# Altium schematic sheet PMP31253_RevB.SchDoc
size 431 x 279 mm; Date: Not shown in title block; ApprovedBy: Not shown in title block; CheckedBy: Not shown in title block; Author: Not shown in title block; CompanyName: Not shown in title block; Engineer: Not shown in title block; Organization: Not shown in title block; Address1: Not shown in title block; Address2: Not shown in title block; Address3: Not shown in title block; Address4: Not shown in title block; DocumentNumber: 2; Revision: Use project parameter SCH_Rev; SheetNumber: 1; SheetTotal: 1; PageSetup: Record=PageOptions¦CenterHorizontal=True¦CenterVertical=True¦PrintScale=1.00¦XCorrection=1.00¦YCorrection=1.00¦PrintKind=0¦BorderSize=5000000¦LeftOffset=0¦BottomOffset=0¦Orientation=2¦PaperLength=1000¦PaperWidth=1000¦Scale=100¦PaperSource=15¦PrintQuality=600¦MediaType=1¦DitherType=10¦PaperKind=Letter¦PrintScaleMode=1
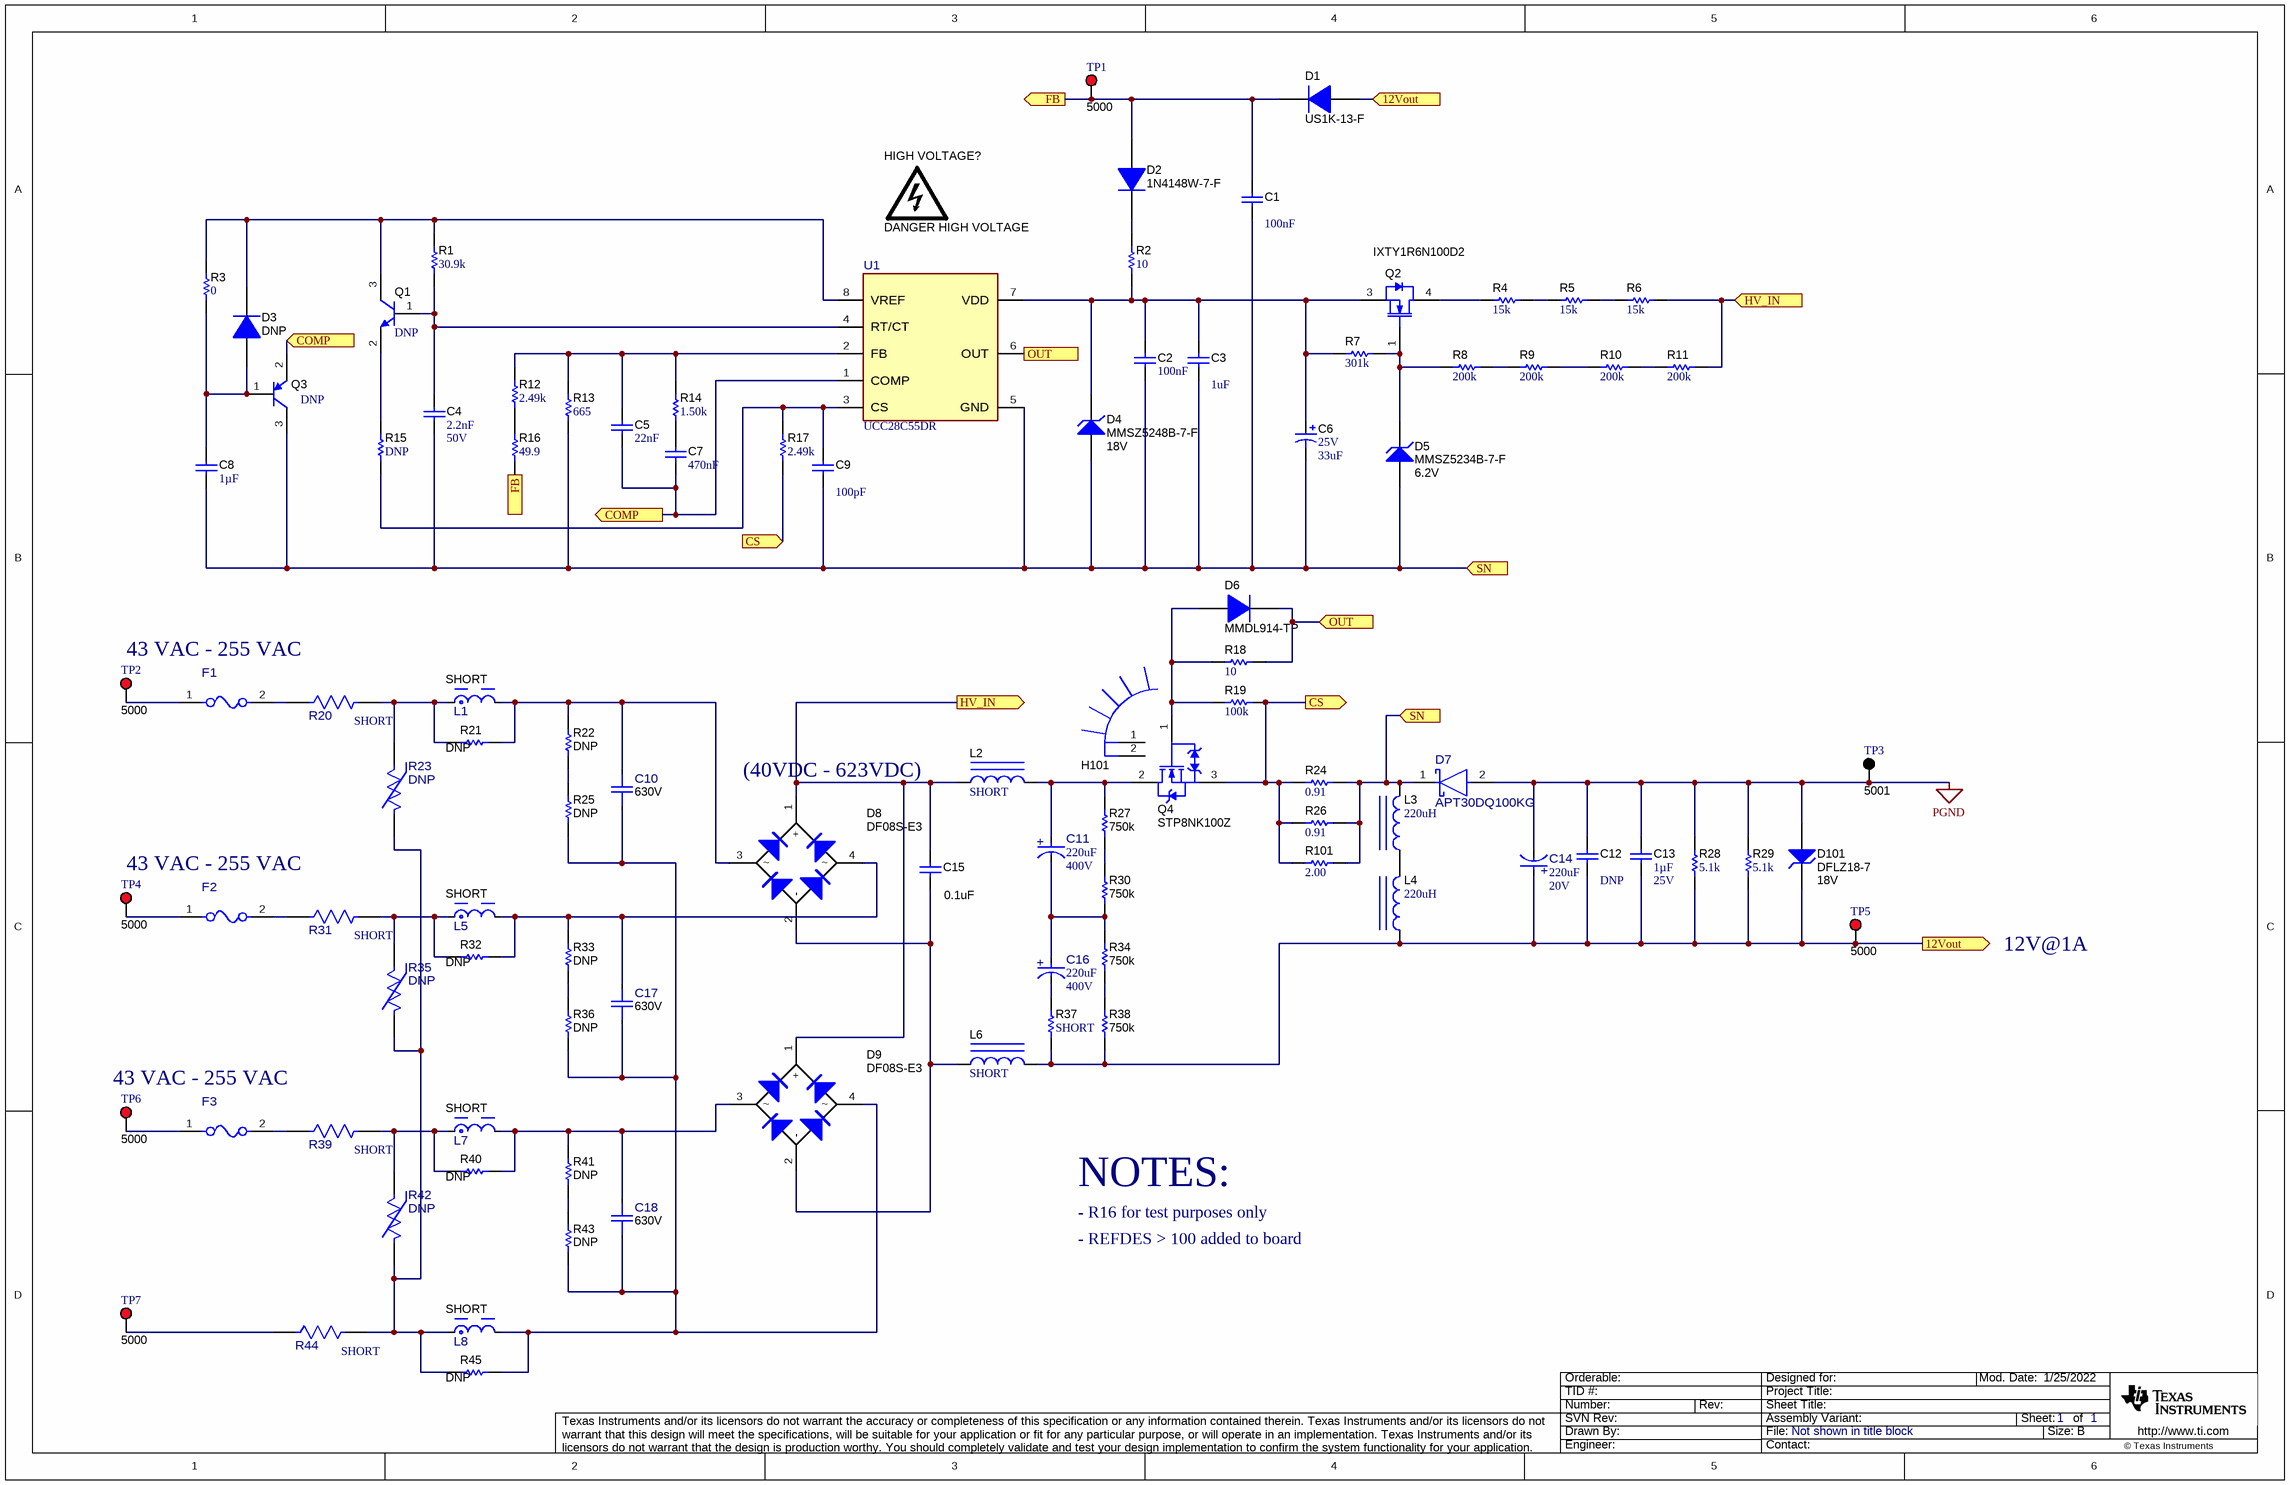
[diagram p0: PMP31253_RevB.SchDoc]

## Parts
C1  Cap_F: 100nF  [0805_HV]  (hidden comment: 08055C104KAT2A)
C2  Cap_F: 100nF  [0805_HV]  (hidden comment: C0805C104J5RACTU)
C3  ValueDisplayed: 1uF  [1206]  (hidden comment: GRM31MR71H105KA88L)
C4  Cap_F: 2.2nF  VDC_V: 50V  [0603]  (hidden comment: GRM188R71H222KA01D)
C5  Cap_F: 22nF  [0603]  (hidden comment: C0603X223K5RACTU)
C6  VDC_V: 25V  ValueDisplayed: 33uF  [CAPSMT_62_F55]  (hidden comment: EMVY250ADA330MF55G)
C7  Cap_F: 470nF  [0603]  (hidden comment: C1608X7R1H474K080AC)
C8  Cap_F: 1µF  [0805_HV]  (hidden comment: GRM21BR71H105KA12L)
C9  ValueDisplayed: 100pF  [0603]  (hidden comment: GRM1885C1H101JA01D)
C10  VDC_V: 630V  [FP-890334025027RP_RADIAL-MFG]  (hidden comment: 890334025027RP)
C11  ValueDisplayed: 220uF  VDC_V: 400V  [FP-EKMQ401VSN221MP45S_RADIAL-MFG]  (hidden comment: EKMQ401VSN221MP45S)
C12  GCM31MR71E105KA37L  [1206]  (value not drawn)
C13  Cap_F: 1µF  VDC_V: 25V  [0805_HV]  (hidden comment: GRM21BR71E105KA99L)
C14  ValueDisplayed: 220uF  VDC_V: 20V  [FP-A768KE227M1DLAE029_SMT_CAP_8MM3_8MM3-MFG]  (hidden comment: A768KE227M1DLAE029)
C15  value 0.1uF  [B32913_2650x700x1600]  (hidden comment: B32913C5104K000)
C16  ValueDisplayed: 220uF  VDC_V: 400V  [FP-EKMQ401VSN221MP45S_RADIAL-MFG]  (hidden comment: EKMQ401VSN221MP45S)
C17  VDC_V: 630V  [FP-890334025027RP_RADIAL-MFG]  (hidden comment: 890334025027RP)
C18  VDC_V: 630V  [FP-890334025027RP_RADIAL-MFG]  (hidden comment: 890334025027RP)
D1  US1K-13-F  [SMA]
D2  1N4148W-7-F  [SOD-123]
D3  DNP  [SOD-323]
D4  MMSZ5248B-7-F  value 18V  [SOD-123]
D5  MMSZ5234B-7-F  value 6.2V  [SOD-123]
D6  MMDL914-TP  [SOD-323]
D7  APT30DQ100KG  [FP-C6D04065A_TO-220-2-MFG]
D8  DF08S-E3  [DF-S]
D9  DF08S-E3  [DF-S]
D101  DFLZ18-7  value 18V  [PowerDI123]
F1  04611.25ER  [FP-04611.25ER_SMT_FUSE_10MM10_3MM12-MFG]  (value not drawn)
F2  04611.25ER  [FP-04611.25ER_SMT_FUSE_10MM10_3MM12-MFG]  (value not drawn)
F3  04611.25ER  [FP-04611.25ER_SMT_FUSE_10MM10_3MM12-MFG]  (value not drawn)
H101  V6560X  [ASMN_V6560X]  (value not drawn)
HIGH_VOLTAGE?  DANGER HIGH VOLTAGE  [IEC_HighVoltage_Small]  (no BOM)
L1  value SHORT  [FP-7447471222_RADIAL-MFG]  (hidden comment: 7447471222)
L2  ValueDisplayed: SHORT  [WE-TI_1014]  (hidden comment: 7447480101)
L3  ValueDisplayed: 220uH  [WE_PD-HV_1210]  (hidden comment: 7687709221)
L4  ValueDisplayed: 220uH  [WE_PD-HV_1210]  (hidden comment: 7687709221)
L5  value SHORT  [FP-7447471222_RADIAL-MFG]  (hidden comment: 7447471222)
L6  ValueDisplayed: SHORT  [WE-TI_1014]  (hidden comment: 7447480101)
L7  value SHORT  [FP-7447471222_RADIAL-MFG]  (hidden comment: 7447471222)
L8  value SHORT  [FP-7447471222_RADIAL-MFG]  (hidden comment: 7447471222)
Q1  value DNP  [SOT-23]  (hidden comment: MMBT3904-7-F)
Q2  IXTY1R6N100D2  [DPAK]
Q3  value DNP  [SOT-23]  (hidden comment: MMBT2907A)
Q4  STP8NK100Z  [TO-220AB]
R1  ValueDisplayed: 30.9k  [0603]  (hidden comment: CRCW060330K9FKEA)
R2  ValueDisplayed: 10  [0805_HV]  (hidden comment: RC0805JR-0710RL)
R3  ValueDisplayed: 0  [0603]  (hidden comment: CRCW06030000Z0EA)
R4  ValueDisplayed: 15k  [PR03]  (hidden comment: PR03000201502JAC00)
R5  ValueDisplayed: 15k  [PR03]  (hidden comment: PR03000201502JAC00)
R6  ValueDisplayed: 15k  [PR03]  (hidden comment: PR03000201502JAC00)
R7  ValueDisplayed: 301k  [1206]  (hidden comment: CRCW1206301KFKEA)
R8  ValueDisplayed: 200k  [1206]  (hidden comment: CRCW1206200KJNEA)
R9  ValueDisplayed: 200k  [1206]  (hidden comment: CRCW1206200KJNEA)
R10  ValueDisplayed: 200k  [1206]  (hidden comment: CRCW1206200KJNEA)
R11  ValueDisplayed: 200k  [1206]  (hidden comment: CRCW1206200KJNEA)
R12  ValueDisplayed: 2.49k  [0603]  (hidden comment: CRCW06032K49FKEA)
R13  ValueDisplayed: 665  [0603]  (hidden comment: CRCW0603665RFKEA)
R14  ValueDisplayed: 1.50k  [0603]  (hidden comment: CRCW06031K50FKEA)
R15  CRCW06031M50JNEA  [0603]  (value not drawn)
R16  ValueDisplayed: 49.9  [0603]  (hidden comment: CRCW060349R9FKEA)
R17  ValueDisplayed: 2.49k  [0603]  (hidden comment: CRCW06032K49FKEA)
R18  ValueDisplayed: 10  [0805_HV]  (hidden comment: CRCW080510R0JNEA)
R19  ValueDisplayed: 100k  [0603]  (hidden comment: CRCW0603100KFKEA)
R20  Res_ohm: SHORT  [FP-SQMW547RJ_RADIAL-MFG]  (hidden comment: SQMW5xxx)
R21  value DNP  [1206]  (hidden comment: CRCW120610K0FKEAHP)
R22  ValueDisplayed: DNP  [1206]  (hidden comment: CRCW1206100KJNEA)
R23  DNP  [FP-B72210S0461K101_RADIAL-MFG]
R24  ValueDisplayed: 0.91  [1210]  (hidden comment: ERJ-14BQ)
R25  ValueDisplayed: DNP  [1206]  (hidden comment: CRCW1206100KJNEA)
R26  ValueDisplayed: 0.91  [1210]  (hidden comment: ERJ-14BQ)
R27  ValueDisplayed: 750k  [1206]  (hidden comment: CRCW1206)
R28  ValueDisplayed: 5.1k  [1206]  (hidden comment: CRCW12065K10JNEA)
R29  ValueDisplayed: 5.1k  [1206]  (hidden comment: CRCW12065K10JNEA)
R30  ValueDisplayed: 750k  [1206]  (hidden comment: CRCW1206)
R31  Res_ohm: SHORT  [FP-SQMW547RJ_RADIAL-MFG]  (hidden comment: SQMW5xxx)
R32  value DNP  [1206]  (hidden comment: CRCW120610K0FKEAHP)
R33  ValueDisplayed: DNP  [1206]  (hidden comment: CRCW1206100KJNEA)
R34  ValueDisplayed: 750k  [1206]  (hidden comment: CRCW1206)
R35  DNP  [FP-B72210S0461K101_RADIAL-MFG]
R36  ValueDisplayed: DNP  [1206]  (hidden comment: CRCW1206100KJNEA)
R37  ValueDisplayed: SHORT  [2512]  (hidden comment: CRM2512-FX-15R0)
R38  ValueDisplayed: 750k  [1206]  (hidden comment: CRCW1206)
R39  Res_ohm: SHORT  [FP-SQMW547RJ_RADIAL-MFG]  (hidden comment: SQMW5xxx)
R40  value DNP  [1206]  (hidden comment: CRCW120610K0FKEAHP)
R41  ValueDisplayed: DNP  [1206]  (hidden comment: CRCW1206100KJNEA)
R42  DNP  [FP-B72210S0461K101_RADIAL-MFG]
R43  ValueDisplayed: DNP  [1206]  (hidden comment: CRCW1206100KJNEA)
R44  Res_ohm: SHORT  [FP-SQMW547RJ_RADIAL-MFG]  (hidden comment: SQMW5xxx)
R45  value DNP  [1206]  (hidden comment: CRCW120610K0FKEAHP)
R101  ValueDisplayed: 2.00  [1210]  (hidden comment: ERJ-14BQF2R0U)
TP1  5000  [Keystone5000]
TP2  5000  [Keystone5000]
TP3  5001  [Keystone5001]
TP4  5000  [Keystone5000]
TP5  5000  [Keystone5000]
TP6  5000  [Keystone5000]
TP7  5000  [Keystone5000]
U1  UCC28C55DR  [D0008A-MFG]

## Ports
12Vout (in), 12Vout (out), COMP (in), COMP (out), CS (in), CS (out), FB (in), FB (out), HV_IN (in), HV_IN (out), OUT (in), OUT (out), SN (in)

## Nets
PGND: C12.1 C13.1 C14.1(CATHODE) D7.2(ANODE) D101.2(A) R28.2 R29.2 TP3.1
12Vout: C12.2 C13.2 C14.2(ANODE) D1.2(A) D101.1(K) L4.1 L6.2 R28.1 R29.1 R37.1 R38.1 TP5.1 ; port 12Vout
COMP: C5.2 C7.2 Q3.2(E) U1.1(COMP) ; port COMP
CS: Q4.3(S) R17.1 R19.2 R24.1 R26.1 R101.1 ; port CS
FB: C1.1 D1.1(K) D2.2(A) R16.1 TP1.1 ; port FB
HV_IN: C15.1 D8.1(+) D9.1(+) L2.1 R6.2 R11.2 ; port HV_IN
OUT: D6.1(K) R18.2 U1.6(OUT) ; port OUT
SN: C1.2 C2.2 C3.2 C4.2 C6.2(-) C8.2 C9.2 D4.2(A) D5.2(A) D7.1(CATHODE) L3.2 Q3.3(C) R13.1 R24.2 R26.2 R101.2 U1.5(GND) ; port SN
NetC2_1: C2.1 C3.1 C6.1(+) D4.1(K) Q2.3(S) R2.1 R7.1 U1.7(VDD)
NetC4_1: C4.1 Q1.1(B) R1.1 U1.4(RT/CT)
NetC5_1: C5.1 R12.2 R13.2 R14.2 U1.2(FB)
NetC7_1: C7.1 R14.1
NetC8_1: C8.1 D3.2(A) Q3.1(B) R3.1
NetC9_1: C9.1 R15.1 R17.2 U1.3(CS)
NetC10_1: C10.1 C17.1 C18.1 D9.4 L8.2 R25.1 R36.1 R43.1 R45.2
NetC10_2: C10.2 D8.3 L1.2 R21.2 R22.2
NetC11_1: C11.1(CATHODE) C16.2(ANODE) R30.1 R34.2
NetC11_2: C11.2(ANODE) L2.2 Q4.2(D) R27.2
NetC15_2: C15.2 D8.2(-) D9.2(-) L6.1
NetC16_1: C16.1(CATHODE) R37.2
NetC17_2: C17.2 D8.4 L5.2 R32.2 R33.2
NetC18_2: C18.2 D9.3 L7.2 R40.2 R41.2
NetD2_1: D2.1(K) R2.2
NetD3_1: D3.1(K) Q1.3(C) R1.2 R3.2 U1.8(VREF)
NetD5_1: D5.1(K) Q2.1(G) R7.2 R8.1
NetD6_2: D6.2(A) Q4.1(G) R18.1 R19.1
NetF1_1: F1.1 TP2.1
NetF1_2: F1.2 R20.1
NetF2_1: F2.1 TP4.1
NetF2_2: F2.2 R31.1
NetF3_1: F3.1 TP6.1
NetF3_2: F3.2 R39.1
NetL1_1: L1.1 R20.2 R21.1 R23.2
NetL3_1: L3.1 L4.2
NetL5_1: L5.1 R31.2 R32.1 R35.2
NetL7_1: L7.1 R39.2 R40.1 R42.2
NetL8_1: L8.1 R23.1 R35.1 R42.1 R44.2 R45.1
NetQ1_2: Q1.2(E) R15.2
NetQ2_4: Q2.4(D) R4.1
NetR4_2: R4.2 R5.1
NetR5_2: R5.2 R6.1
NetR8_2: R8.2 R9.1
NetR9_2: R9.2 R10.1
NetR10_2: R10.2 R11.1
NetR12_1: R12.1 R16.2
NetR22_1: R22.1 R25.2
NetR27_1: R27.1 R30.2
NetR33_1: R33.1 R36.2
NetR34_1: R34.1 R38.2
NetR41_1: R41.1 R43.2
NetR44_1: R44.1 TP7.1

Not connected (* = marked no-connect by the designer): H101 1 2

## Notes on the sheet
- 43 VAC - 255 VAC
- (40VDC - 623VDC)
- 12V@1A
- NOTES:
- - R16 for test purposes only
- - REFDES > 100 added to board

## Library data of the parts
C1 = CMP-0007632-2: CAP, CERM, 0.1 uF, 50 V, +/- 10%, X7R, 0805; Manufacturer: AVX; TaMin_C: -55°C; ESR_ohm: 24m; Polarized: N; SizeAreaWB_mm2: 6.75; Value1: 0.024 ohm; U/M: EA; Value: 0.1uF; TaMax_C: 125°C; SizeZ_mm: 1.45; SizeX_mm: 2; SizeY_mm: 1.25; Cap_Case: 0805; Value2: 50V; SizeArea_mm2: 2.5; AEC Category: Q200
C2 = CMP-0007721-2: CAP, CERM, 0.1 uF, 50 V, +/- 5%, X7R, 0805; Manufacturer: Kemet; TaMin_C: -55°C; ESR_ohm: 64m; Polarized: N; SizeAreaWB_mm2: 6.75; Value1: 0.064 ohm; U/M: EA; Value: 0.1uF; TaMax_C: 125°C; SizeZ_mm: 1.45; SizeX_mm: 2; SizeY_mm: 1.25; Cap_Case: 0805; Value2: 50V; SizeArea_mm2: 2.5; IRMS_A: 1.64A; AEC Category: Q200
C3 = CMP-0008992-2: CAP, CERM, 1 uF, 50 V, +/- 10%, X7R, 1206; Manufacturer: MuRata; TaMin_C: -55°C; Polarized: N; SizeAreaWB_mm2: 10.92; Value1: Unknown; U/M: EA; Value: 1uF; TaMax_C: 125°C; SizeZ_mm: 1.35; SizeX_mm: 3.2; SizeY_mm: 1.6; Value2: 50V; SizeArea_mm2: 5.12; Cap_F: 1µF; AEC Category: Q200
C4 = CMP-0007443-4: CAP, CERM, 2200 pF, 50 V, +/- 10%, X7R, 0603; Manufacturer: MuRata; TaMin_C: -55°C; Polarized: N; SizeAreaWB_mm2: 4.68; Value1: Unknown; U/M: EA; Value: 2200pF; TaMax_C: 125°C; SizeZ_mm: 1; SizeX_mm: 1.6; SizeY_mm: 0.8; SizeArea_mm2: 1.28; AEC Category: Q200
C5 = CMP-0006984-4: CAP, CERM, 0.022 uF, 50 V, +/- 10%, X7R, 0603; Manufacturer: Kemet; TaMin_C: -55°C; Polarized: N; SizeAreaWB_mm2: 4.68; Value1: Unknown; U/M: EA; TaMax_C: 125°C; SizeZ_mm: 1; SizeX_mm: 1.6; SizeY_mm: 0.8; Value2: 50V; SizeArea_mm2: 1.28; AEC Category: Q200
C6 = CMP-0010994-1: CAP, AL, 33 uF, 25 V, +/- 20%, 1 ohm, SMD; Manufacturer: Chemi-Con; TaMin_C: -55°C; ESR_ohm: 1; Polarized: Y; SizeAreaWB_mm2: 77.44; Value1: 1 ohm; U/M: EA; Value: 33uF; TaMax_C: 105°C; SizeZ_mm: 5.5; SizeX_mm: 6.8; Cap_Case: F55; SizeArea_mm2: 46.24; CompType: Capacitor; Cap_F: 33µF; IRMS_A: 140mA; AEC Category: Q200
C7 = CMP-0007050-4: CAP, CERM, 0.47 uF, 50 V, +/- 10%, X7R, 0603; Manufacturer: TDK; TaMin_C: -55°C; ESR_ohm: 10.974m; Polarized: N; SizeAreaWB_mm2: 4.68; Value1: 0.010974 ohm; U/M: EA; Value: 0.47uF; TaMax_C: 125°C; SizeZ_mm: 1; SizeX_mm: 1.6; SizeY_mm: 0.8; Value2: 50V; SizeArea_mm2: 1.28; IRMS_A: 1.5748A; AEC Category: Q200
C8 = CMP-0008350-2: CAP, CERM, 1 uF, 50 V, +/- 10%, X7R, 0805; Manufacturer: MuRata; TaMin_C: -55°C; Polarized: N; SizeAreaWB_mm2: 6.75; Value1: Unknown; U/M: EA; Value: 1uF; TaMax_C: 125°C; SizeZ_mm: 1.45; SizeX_mm: 2; SizeY_mm: 1.25; Cap_Case: 0805; Value2: 50V; SizeArea_mm2: 2.5; AEC Category: Q200
C9 = CMP-0007171-4: CAP, CERM, 100 pF, 50 V, +/- 5%, C0G/NP0, 0603; Manufacturer: MuRata; TaMin_C: -55°C; Polarized: N; SizeAreaWB_mm2: 4.68; Value1: Unknown; U/M: EA; Value: 100pF; TaMax_C: 125°C; SizeZ_mm: 1; SizeX_mm: 1.6; SizeY_mm: 0.8; Value2: 50V; SizeArea_mm2: 1.28; AEC Category: Q200
C10 C17 C18 = CMP-0096484-1: 0.22 µF Film Capacitor 630V Polypropylene (PP), Metallized Radial; Manufacturer: Wurth Electronics; AEC Qualified: No; Cap_F: 220nF; Voltage Ac Rating X: 310V; SizeZ_mm: 12mm; Tolerance_%: 10%; Value: 220nF; VAC_X: X2
C11 C16 = CMP-0001412-1: Cap Aluminum Lytic 220uF 400V 20% (22 X 45mm) Snap-In 10mm 1100mA 2000h 105°C; Manufacturer: United Chemi-Con; AEC Qualified: No; Cap_F: 220µF; IRMS_A: 1.1A; SizeZ_mm: 47mm; Dissipation Factor: 15%; Leakage Current: 889uA; Life: 2000Hours; Value: 220µF
C12 = CMP-0008817-1: DNP; Manufacturer: MuRata; TaMin_C: -55°C; Polarized: N; TempCo: X7R; SizeAreaWB_mm2: 10.92; Value1: Unknown; U/M: EA; TaMax_C: 125°C; Tolerance_%: 10%; SizeZ_mm: 1.35; SizeX_mm: 3.2; SizeY_mm: 1.6; Value2: 25V; SizeArea_mm2: 5.12; AEC Qualified: Y; Cap_F: 1µF; AEC Grade: 1; AEC Category: Q200
C13 = CMP-0008336-1: CAP, CERM, 1 uF, 25 V, +/- 10%, X7R, 0805; Manufacturer: MuRata; TaMin_C: -55°C; Polarized: N; SizeAreaWB_mm2: 6.75; Value1: Unknown; U/M: EA; Value: 1uF; TaMax_C: 125°C; SizeZ_mm: 1.45; SizeX_mm: 2; SizeY_mm: 1.25; Cap_Case: 0805; SizeArea_mm2: 2.5; AEC Category: Q200
C14 = CMP-0001409-1: 220 µF 20 V Aluminum - Polymer Capacitors Radial, Can - SMD 29mOhm 2000 Hrs @ 125°C; Manufacturer: KEMET; AEC Qualified: No; Cap_F: 220µF; IRMS_A: 1.6A; SizeZ_mm: 7mm; Tolerance_%: 20%; Esr: 29m; Leakage Current: 880uA; Life: 2000Hours; Value: 220µF
C15 = CMP-0012372-1: CAP, Film, 0.1 uF, 1000 V, +/- 10%, TH; Manufacturer: TDK; TaMin_C: -40°C; Polarized: N; SizeAreaWB_mm2: 256.5; Value1: Unknown; U/M: EA; TaMax_C: 110°C; SizeZ_mm: 16; SizeX_mm: 26.5; SizeY_mm: 7; Cap_Case: 26.5x7x16mm; Value2: 1000V; SizeArea_mm2: 185.5; Cap_F: 100nF; VDC_V: 1kV; AEC Category: Q200
D1 = CMP-0076980-2: Diode, Fast Rectifier, 800 V, 1 A, SMA; Manufacturer: Diodes Inc.; AEC Category: Q101; Io_A: 1A; Green_Lifecycle: Not Set; Value2: 1.7V; SizeAreaWB_mm2: 37.3428; Green_REACh: Incomplete; Vr_V: 800V; SizeY_mm: 2.92; Value: 800V; TJmax_C: 150°C; SizeZ_mm: 2.87; SizeX_mm: 5.59; SizeArea_mm2: 16.3228
D2 = CMP-0029001-1: Diode, Ultrafast, 100 V, 0.15 A, SOD-123; Manufacturer: Diodes Inc.; Io_A: 150mA; Green_Lifecycle: Active; SizeAreaWB_mm2: 13.095; Vr_V: 100V; Green_REACh: Passed; Value1: 0.15A; TJmax_C: 150°C; U/M: EA; Value: 100V; SizeZ_mm: 1.35; SizeX_mm: 3.85; SizeY_mm: 1.7; Vf_V: 1.25V; SizeArea_mm2: 6.545; AEC Category: Q101
D3 = CMP-0082069-2: Manufacturer: Micro Commercial Components; AEC Category: Q101; AEC Qualified: N; Value1: 0.15A; SizeX_mm: 2.7; Vr_V: 75V; Vf_V: 1V; SizeZ_mm: 1; SizeY_mm: 1.35; SizeAreaWB_mm2: 8.695; Type: Switching; TJmax_C: 150°C; RJC_CperW: 625; Io_A: 150mA; SizeArea_mm2: 3.645
D4 = CMP-0005755-4: Diode, Zener, 18 V, 500 mW, SOD-123; Manufacturer: Diodes Inc.; SizeAreaWB_mm2: 13.095; RJA_CperW: 350; SizeArea_mm2: 6.545; Power_W: 500mW; SizeX_mm: 3.85; SizeY_mm: 1.7; AEC Category: Q101; Value1: 0.5W; SizeZ_mm: 1.35
D5 = CMP-0005805-3: Diode, Zener, 6.2 V, 500 mW, SOD-123; Manufacturer: Diodes Inc.; SizeY_mm: 1.7; AEC Category: Q101; SizeAreaWB_mm2: 13.095; SizeZ_mm: 1.35; SizeArea_mm2: 6.545; RJA_CperW: 350; Power_W: 500mW; Value1: 0.5W; SizeX_mm: 3.85
D6 = CMP-0029045-1: Diode, Switching, 100 V, 0.2 A, SOD-323; Manufacturer: Micro Commercial Components; Io_A: 200mA; Green_Lifecycle: Not Set; SizeAreaWB_mm2: 8.695; Vr_V: 100V; Green_REACh: Incomplete; Value1: 0.2A; TJmax_C: 150°C; U/M: EA; Value: 100V; SizeZ_mm: 1; SizeX_mm: 2.7; SizeY_mm: 1.35; Vf_V: 1V; SizeArea_mm2: 3.645; AEC Category: Q101
D7 = CMP-0094567-1: Diode 1kV Through Hole TO-220-2; Part Number: APT30DQ100GK; Manufacturer: Wolfspeed; Standoff Height: 3.302mm; Forward Current: 30A; TJmax_C: 175°C; Vf_V: 1000V; SizeZ_mm: 19.431mm; AEC Qualified: No
D8 D9 = CMP-0029219-1: Diode, Switching-Bridge, 800 V, 1 A, DF-S; Manufacturer: Vishay-Semiconductor; Io_A: 1A; SizeAreaWB_mm2: 98.794; Vr_V: 600V; Green_REACh: Incomplete; TJmax_C: 150°C; U/M: EA; Value: 800V; Green_Lifecycle: Not Set; SizeZ_mm: 3.4; SizeX_mm: 7.4; SizeY_mm: 8.51; Vf_V: 1.1V; SizeArea_mm2: 62.974; AEC Category: Q101; RJC_CperW: 15
D101 = CMP-0005413-4: Diode, Zener, 18 V, 1 W, PowerDI123; Manufacturer: Diodes Inc.; RJA_CperW: 110; Power_W: 1W; SizeAreaWB_mm2: 13.066; AEC Category: Q101; SizeZ_mm: 0.98; SizeX_mm: 3.7; SizeY_mm: 1.78; SizeArea_mm2: 6.586
F1-F3 = CMP-0001488-1: Fuse Chip Slow Blow Acting 1.25A 600V SMD Solder Pad 10.1 X 3.12 X 3.12mm Ceramic T/R; Manufacturer: Littelfuse Inc; Interrupt_AC: 60A; Interrupt_DC: 100A; MeltingTyp: 16.5A2Sec; AEC Qualified: No; Res_ohm: 0.104Ω
H101 = CMP-0004065-1: HEATSINK, ALUM, TO-220; PartNumber: Heatsink TO220
HIGH_VOLTAGE? = CMP-0074835-1: IEC 61010-1 High Voltage Warning; SymbolCreator: a0412235
L1 L5 L7 L8 = CMP-0096506-1: 2.2 mH Shielded Drum Core, Wirewound Inductor 400 mA 2.7Ohm Max Radial, Vertical Cylinder; Manufacturer: Wurth Electronics; Self Resonant Frequency: 740kHz; Ind_H: 2.2mH; DCR_ohm: 5.7; AEC Qualified: Yes; Irms: 0.31A; Tolerance_%: 10%; TaMax_C: +85°C; TaMin_C: -40°C; AEC Grade: Grade 1; SizeZ_mm: 11.5mm; Shrouded: true; Test Frequency: 10kHz; Isat: 0.46A; Material: Ferrite
L2 L6 = CMP-0064523-2: Inductor, Wirewound, Ferrite, 100 uH, 2.4 A, 0.1 ohm, TH; Manufacturer: Wurth Elektronik; Isat: 2.5A @ 10% inductance drop; Irms: 2.4A @ 40C rise; Green_Lifecycle: Active; SizeAreaWB_mm2: 156.25; DCR_ohm: 0.1; Green_REACh: Passed; Value1: 0.1 ohm; Value: 100uH; Imax_A: 2.4A; SizeZ_mm: 14.5; SizeX_mm: 10.5; SizeArea_mm2: 110.25; Ind_H: 100µH; AEC Category: Q200
L3 L4 = CMP-0064845-2: Inductor, Wirewound, 220 uH, 1.3 A, 0.3 ohm, SMD; Manufacturer: Wurth Elektronik; Isat: 2A @ 10% inductance drop; Irms: 1.3A @ 40C rise; Green_Lifecycle: Active; SizeAreaWB_mm2: 196; DCR_ohm: 0.3; Green_REACh: Passed; Value1: 0.3 ohm; Value: 220uH; Imax_A: 1.3A; SizeZ_mm: 10.5; SizeX_mm: 12; SizeArea_mm2: 144; Ind_H: 220µH; AEC Qualified: N; AEC Category: Q200
Q1 = CMP-0000387-2: Transistor, NPN, 40 V, 0.2 A, SOT-23; Manufacturer: Diodes Inc.; TaMax_C: 150°C; Value2: 400; Value1: 0.2 A; Vcesat1_V: 200mV; SizeX_mm: 2.5; SizeY_mm: 3; TaMin_C: -55°C; IcRated_A: 200mA; CompType: BJT; SizeZ_mm: 1.1; SizeArea_mm2: 7.5; NPN: 1; Vceo_V: 40V; PNP: 0; SizeAreaWB_mm2: 14; U/M: EA
Q2 = CMP-0067585-1: MOSFET, N-CH, 1000V, DPAK; Alternate Manufacturer: None; Manufacturer: IXYS; QgTyp_nC: 27.0; SizeAreaWB_mm2: 101.7114; Value1: ? ohm; VdsMax_V: 1kV; U/M: EA; SizeArea_mm2: 64.8114; ChType: N
Q3 = CMP-0000331-2: Transistor, PNP, 60 V, 0.8 A, SOT-23; Manufacturer: Fairchild Semiconductor; TaMax_C: 150°C; Vcesat1_V: 1.6V; SizeX_mm: 2.5; SizeY_mm: 3; TaMin_C: -55°C; IcRated_A: 800mA; CompType: BJT; SizeZ_mm: 1.1; HfeMax: 300; SizeArea_mm2: 7.5; NPN: 0; Vceo_V: 60V; PNP: 1; AEC Category: Q101; SizeAreaWB_mm2: 14; U/M: EA
Q4 = CMP-0001292-3: MOSFET, N-CH, 1000 V, 6.5 A, TO-220AB; Alternate Manufacturer: None; Manufacturer: STMicroelectronics; SizeZ_mm: 19.4; ChType: N; Value2: 73 nC; VdsMax_V: 1kV; SizeX_mm: 10.2; SizeY_mm: 4.5; Vgs_V: 30V; Value: 1000V; SizeArea_mm2: 45.9; AEC Category: Q101; IdsMax_A: 6.5A; SizeAreaWB_mm2: 79.3; U/M: EA; QgTyp_nC: 73
R1 = CMP-0022325-4: RES, 30.9 k, 1%, 0.1 W, AEC-Q200 Grade 0, 0603; Manufacturer: Vishay-Dale; Power_W: 100mW; TempCo: 100 ppm/C; Value_Code: 30k9; Value: 30.9k; EIA_Code: E96; SizeX_mm: 1.6; SizeY_mm: 0.8; SizeZ_mm: 1; Value2: 0.1W; SizeArea_mm2: 1.28; AEC Qualified: Y; VDC_V: 75V; AEC Category: Q200; AEC Grade: 0
R2 = CMP-0020804-2: RES, 10, 5%, 0.125 W, 0805; Manufacturer: Yageo America; Power_W: 125mW; TempCo: 200 ppm/C; Value_Code: 10R0; U/M: EA; Value: 10; EIA_Code: E24; SizeX_mm: 2; SizeY_mm: 1.25; SizeZ_mm: 1.45; Value2: 0.125W; SizeArea_mm2: 2.5; VDC_V: 150V; AEC Category: Q200
R3 = CMP-0025697-4: RES, 0, 5%, 0.1 W, AEC-Q200 Grade 0, 0603; Manufacturer: Vishay-Dale; Power_W: 100mW; TempCo: 200 ppm/C; Value_Code: 0000; Value: 0; EIA_Code: E24; SizeX_mm: 1.6; SizeY_mm: 0.8; SizeZ_mm: 1; Value2: 0.1W; SizeArea_mm2: 1.28; AEC Qualified: Y; VDC_V: 75V; AEC Category: Q200
R4-R6 = CMP-0014427-2: RES, 15 k, 5%, 3 W, D5.20xL16.70mm; Manufacturer: Vishay-Bccomponents; Power_W: 3W; TempCo: 250 ppm/C; Value_Code: 15k0; U/M: EA; Value: 15k; EIA_Code: E24; AEC Qualified: N; VDC_V: 750V; AEC Category: Q200
R7 = CMP-0016895-2: RES, 301 k, 1%, 0.25 W, 1206; Manufacturer: Vishay-Dale; Power_W: 250mW; TempCo: 100 ppm/C; U/M: EA; Value: 301k; EIA_Code: E96; SizeX_mm: 3.2; SizeY_mm: 1.6; SizeZ_mm: 1.35; Value2: 0.25W; SizeArea_mm2: 5.12; VDC_V: 200V; AEC Category: Q200
R8-R11 = CMP-0018624-3: RES, 200 k, 5%, 0.25 W, AEC-Q200 Grade 0, 1206; Manufacturer: Vishay-Dale; Power_W: 250mW; TempCo: 200 ppm/C; Value: 200k; EIA_Code: E24; SizeX_mm: 3.2; SizeY_mm: 1.6; SizeZ_mm: 1.35; Value2: 0.25W; SizeArea_mm2: 5.12; AEC Qualified: Y; VDC_V: 200V; AEC Category: Q200; AEC Grade: 0
R12 R17 = CMP-0022277-4: RES, 2.49 k, 1%, 0.1 W, AEC-Q200 Grade 0, 0603; Manufacturer: Vishay-Dale; Power_W: 100mW; TempCo: 100 ppm/C; Value_Code: 2k49; Value: 2.49k; EIA_Code: E96; SizeX_mm: 1.6; SizeY_mm: 0.8; SizeZ_mm: 1; Value2: 0.1W; SizeArea_mm2: 1.28; AEC Qualified: Y; VDC_V: 75V; AEC Category: Q200; AEC Grade: 0
R13 = CMP-0022547-5: RES, 665, 1%, 0.1 W, AEC-Q200 Grade 0, 0603; Manufacturer: Vishay-Dale; Power_W: 100mW; TempCo: 100 ppm/C; Value_Code: 665R; Value: 665; EIA_Code: E96; SizeX_mm: 1.6; SizeY_mm: 0.8; SizeZ_mm: 1; Value2: 0.1W; SizeArea_mm2: 1.28; AEC Qualified: Y; VDC_V: 75V; AEC Category: Q200; AEC Grade: 0
R14 = CMP-0022126-4: RES, 1.50 k, 1%, 0.1 W, AEC-Q200 Grade 0, 0603; Manufacturer: Vishay-Dale; Power_W: 100mW; TempCo: 100 ppm/C; Value_Code: 1k50; Value: 1.50k; EIA_Code: E96; Res_ohm: 1.5k; SizeX_mm: 1.6; SizeY_mm: 0.8; SizeZ_mm: 1; Value2: 0.1W; SizeArea_mm2: 1.28; AEC Qualified: Y; VDC_V: 75V; AEC Category: Q200; AEC Grade: 0
R15 = CMP-0025740-1: DNP; Manufacturer: Vishay-Dale; Power_W: 100mW; TempCo: 200 ppm/C; Value_Code: 1M50; Value1: 5%; U/M: EA; EIA_Code: E24; SizeX_mm: 1.6; SizeY_mm: 0.8; SizeZ_mm: 1; Value2: 0.1W; SizeArea_mm2: 1.28; VDC_V: 75V; AEC Category: Q200
R16 = CMP-0022448-4: RES, 49.9, 1%, 0.1 W, AEC-Q200 Grade 0, 0603; Manufacturer: Vishay-Dale; Power_W: 100mW; TempCo: 100 ppm/C; Value_Code: 49R9; Value: 49.9; EIA_Code: E96; SizeX_mm: 1.6; SizeY_mm: 0.8; SizeZ_mm: 1; Value2: 0.1W; SizeArea_mm2: 1.28; AEC Qualified: Y; VDC_V: 75V; AEC Category: Q200; AEC Grade: 0
R18 = CMP-0020448-1: RES, 10, 5%, 0.125 W, 0805; Manufacturer: Vishay-Dale; Power_W: 125mW; TempCo: 200 ppm/C; Value_Code: 10R0; U/M: EA; Value: 10; EIA_Code: E24; SizeX_mm: 2; SizeY_mm: 1.25; SizeZ_mm: 1.45; Value2: 0.125W; SizeArea_mm2: 2.5; VDC_V: 150V; AEC Category: Q200
R19 = CMP-0021990-3: RES, 100 k, 1%, 0.1 W, 0603; Manufacturer: Vishay-Dale; Power_W: 100mW; TempCo: 100 ppm/C; U/M: EA; Value: 100k; EIA_Code: E96; SizeX_mm: 1.6; SizeY_mm: 0.8; SizeZ_mm: 1; Value2: 0.1W; SizeArea_mm2: 1.28; VDC_V: 75V; AEC Category: Q200
R20 R31 R39 R44 = CMP-0087547-1: RESISTOR, 5W, 0R; Manufacturer: TE Connectivity; TempCo: 300ppm/°C; AEC Qualified: No; SizeZ_mm: 26mm; Tolerance_%: 5%
R21 R32 R40 R45 = CMP-0016578-3: RES, 10.0 k, 1%, 0.5 W, AEC-Q200 Grade 0, 1206; Manufacturer: Vishay-Dale; Power_W: 500mW; TempCo: 100 ppm/C; Value_Code: 10k0; EIA_Code: E96; Res_ohm: 10k; SizeX_mm: 3.2; SizeY_mm: 1.6; SizeZ_mm: 1.35; Value2: 0.5W; SizeArea_mm2: 5.12; AEC Qualified: Y; AEC Category: Q200; ValueDisplayed: 10.0k; AEC Grade: 0
R22 R25 R33 R36 R41 R43 = CMP-0018574-3: RES, 5%, 1206; Manufacturer: Vishay-Dale; Power_W: 250mW; TempCo: 200 ppm/C; Value_Code: 100k; Value: TBD; EIA_Code: E24; SizeX_mm: 3.2; SizeY_mm: 1.6; SizeZ_mm: 1.35; Value2: 0.25W; SizeArea_mm2: 5.12; AEC Qualified: Y; VDC_V: 200V; AEC Category: Q200; AEC Grade: 0
R23 R35 R42 = CMP-0001478-1: 750 V 2.5 kA Varistor 1 Circuit Through Hole Disc 10mm; Manufacturer: TDK; PartNumber: B72210S0461K101; SizeZ_mm: 15mm; AEC Qualified: No; Cap_F: 150pF; Clamping Voltage: 1240V; Varistor Voltage: 750V; Vc: 25A; VDC_V: 615V; Voltage Tolerance: 10%
R24 R26 = CMP-0015029-2: RES, 0.91, 1%, 0.5 W, 1210; Manufacturer: Panasonic; Power_W: 500mW; TempCo: 100 ppm/C; SizeAreaWB_mm2: 14.7; U/M: EA; Value: 0.91; EIA_Code: E96; Res_ohm: 2; SizeX_mm: 3.2; SizeY_mm: 2.5; SizeZ_mm: 1.35; Value2: 0.5W; SizeArea_mm2: 8; AEC Qualified: Y; AEC Grade: 0
R27 R30 R34 R38 = CMP-0018574-3: RES, 5%, 1206; Manufacturer: Vishay-Dale; Power_W: 250mW; TempCo: 200 ppm/C; Value_Code: 100k; Value: 750k; EIA_Code: E24; SizeX_mm: 3.2; SizeY_mm: 1.6; SizeZ_mm: 1.35; Value2: 0.25W; SizeArea_mm2: 5.12; AEC Qualified: Y; VDC_V: 200V; AEC Grade: 0
R28 R29 = CMP-0018703-3: RES, 5.1 k, 5%, 0.25 W, AEC-Q200 Grade 0, 1206; Manufacturer: Vishay-Dale; Power_W: 250mW; TempCo: 200 ppm/C; Value_Code: 5k10; Value: 5.1k; EIA_Code: E24; SizeX_mm: 3.2; SizeY_mm: 1.6; SizeZ_mm: 1.35; Value2: 0.25W; SizeArea_mm2: 5.12; AEC Qualified: Y; VDC_V: 200V; AEC Category: Q200; AEC Grade: 0
R37 = CMP-0078952-1: RES, 15, 1%, 2 W, 2512; Manufacturer: Bourns; Value_Code: 200R; SizeArea_mm2: 20.16; AEC Qualified: N; AEC Category: Q200; Res_ohm: 15; Value: SHORT; SizeZ_mm: 0.71; EIA_Code: E96; TempCo: 100 ppm/C; Power_W: 2W; VDC_V: 300V; SizeY_mm: 3.2; SizeX_mm: 6.3
R101 = CMP-0015029-2: RES, 2.00, 1%, 0.5 W, AEC-Q200 Grade 0, 1210; Manufacturer: Panasonic; Power_W: 500mW; TempCo: 100 ppm/C; SizeAreaWB_mm2: 14.7; Value_Code: 2R00; U/M: EA; Value: 2.00; EIA_Code: E96; Res_ohm: 2; SizeX_mm: 3.2; SizeY_mm: 2.5; SizeZ_mm: 1.35; Value2: 0.5W; SizeArea_mm2: 8; AEC Qualified: Y; AEC Grade: 0; AEC Category: Q200
TP1 TP2 TP4-TP7 = CMP-0055137-2: Test Point, Miniature, Red, TH; Manufacturer: Keystone Electronics; Green_REACh: Passed; Green_Lifecycle: Active; ContactFinish: Silver; CNHeader: FALSE; CT: TRUE
TP3 = CMP-0055138-2: Test Point, Miniature, Black, TH; Manufacturer: Keystone Electronics; ContactFinish: Silver; CNHeader: FALSE; Green_Lifecycle: Active; Green_REACh: Passed; CT: TRUE
U1 = CMP-0001407-1: Low-Power Current-Mode High-Performance PWM Controller for Si and SiC MOSFETs; Manufacturer: Texas Instruments; SizeZ_mm: 1.75mm; AEC Qualified: No; Max Duty Cycle: 100%; Max Supply Voltage: 28V; Nominal Supply Current: 1.3mA; Number Of Outputs: 1; Standoff Height: 0.11mm; Switching Frequency: 1MHz; Switching Topology: Boost,Buck,Flyback,Other; TJmax_C: +125°C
